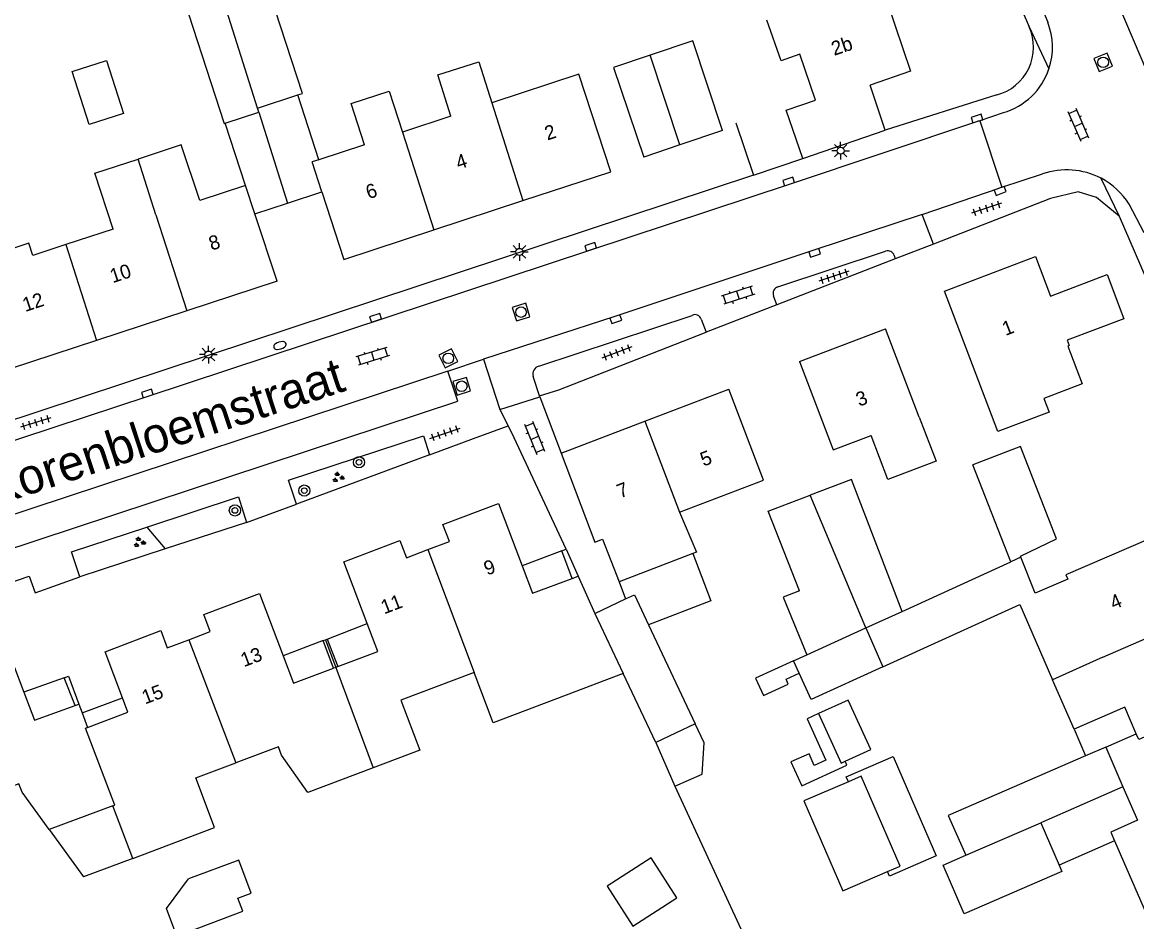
# Model space of a CAD drawing. Extents: x 136000 to 138005, y 398500 to 400500.
# Drawn here: x 137462 to 137540.9, y 398555 to 398618.7 of the extents above; entities that cross this region are included whole.
import ezdxf

# ---------------------------------------------------------------- set-up
doc = ezdxf.new("R2010")
doc.units = 0
for name, color, linetype in [('gg-afsc-muur', 7, 'Continuous'), ('gg-anno-huisnummerreeks BGT', 7, 'Continuous'), ('gg-anno-openbare ruimte label', 7, 'Continuous'), ('gg-bbg-bijgebouw', 7, 'Continuous'), ('gg-bbg-gedigitaliseerde bebouwing', 7, 'Continuous'), ('gg-bbg-gedigitaliseerde bijgebouw', 7, 'Continuous'), ('gg-bbg-hoofdgebouw', 7, 'Continuous'), ('gg-bbg-luifel en loopbrug', 7, 'Continuous'), ('gg-bbg-overig bouwwerk', 7, 'Continuous'), ('gg-bbg-tussenscheiding', 7, 'Continuous'), ('gg-knt-verharding', 7, 'Continuous'), ('gt-grn-groengrens', 7, 'Continuous'), ('gt-grn-vlakafsluiter', 7, 'Continuous'), ('gt-grn-weggrens', 7, 'Continuous'), ('gt-symb-boom', 7, 'Continuous'), ('gt-symb-brandkraan', 7, 'Continuous'), ('gt-symb-groenvak', 7, 'Continuous'), ('gt-symb-klinker verharding', 7, 'Continuous'), ('gt-symb-kolk', 7, 'Continuous'), ('gt-symb-lichtmast', 7, 'Continuous'), ('gt-symb-rioolschacht', 7, 'Continuous'), ('gt-symb-tegel verharding', 7, 'Continuous')]:
    doc.layers.add(name, color=color, linetype=linetype)

# ---------------------------------------------------------------- blocks, each defined once
blk = doc.blocks.new('gt0-RS')
at = {"layer": 'gt-symb-rioolschacht'}
blk.add_lwpolyline([(-0.5, -0.5), (0.5, -0.5), (0.5, 0.5), (-0.5, 0.5)], close=True, dxfattribs=at)
blk.add_circle((0, 0), 0.375, dxfattribs=at)
blk = doc.blocks.new('gt0-KOLK')
at = {"layer": 'gt-symb-kolk'}
blk.add_lwpolyline([(0, 0), (0.375, 0), (0.375, 0.4), (-0.375, 0.4), (-0.375, 0), (0, 0)], dxfattribs=at)
blk = doc.blocks.new('gt0-LMAST')
at = {"layer": 'gt-symb-lichtmast'}
for p, q in [((-0.182, 0.173), (-0.447, 0.438)), ((-0.005, 0.246), (-0.005, 0.621)), ((0.172, 0.173), (0.437, 0.438)), ((-0.255, -0.004), (-0.63, -0.004)), ((-0.182, -0.181), (-0.447, -0.446)), ((-0.005, -0.254), (-0.005, -0.629)), ((0.437, -0.446), (0.172, -0.181)), ((0.245, -0.004), (0.62, -0.004))]:
    blk.add_line(p, q, dxfattribs=at)
blk.add_circle((-0.005, -0.004), 0.25, dxfattribs=at)
blk = doc.blocks.new('gt0-TEG1')
at = {"layer": 'gt-symb-tegel verharding'}
for p, q in [((-1.125, 0), (1.125, 0)), ((-0.9, -0.25), (-0.9, 0.25)), ((-0.45, -0.25), (-0.45, 0.25)), ((0, -0.25), (0, 0.25)), ((0.45, -0.25), (0.45, 0.25)), ((0.9, -0.25), (0.9, 0.25))]:
    blk.add_line(p, q, dxfattribs=at)
blk = doc.blocks.new('gt0-KL1')
at = {"layer": 'gt-symb-klinker verharding'}
for p, q in [((-1.15, 0.3), (1.15, 0.3)), ((-1, -0.3), (-1, 0.3)), ((-0.5, 0.3), (-0.5, 0.45)), ((0, -0.3), (0, 0.3)), ((0.5, 0.3), (0.5, 0.45)), ((1, -0.3), (1, 0.3)), ((-1.15, -0.3), (1.15, -0.3)), ((-0.5, -0.45), (-0.5, -0.3)), ((0.5, -0.45), (0.5, -0.3))]:
    blk.add_line(p, q, dxfattribs=at)
blk = doc.blocks.new('gt0-BR')
at = {"layer": 'gt-symb-brandkraan'}
for centre, radius, start, end in [((-0.244, 0), 0.206, 107.56694, 252.43307), ((0.599, -2.664), 3, 106.89205, 107.56694), ((0, -0.691), 0.938, 73.10799, 106.89205), ((-0.599, -2.664), 3, 72.43309, 73.10799), ((0.244, 0), 0.206, 287.56695, 72.43309), ((0.599, 2.664), 3, 252.43307, 253.10797), ((0, 0.691), 0.938, 253.10797, 286.89206), ((-0.599, 2.664), 3, 286.89206, 287.56695)]:
    blk.add_arc(centre, radius, start, end, dxfattribs=at)
blk = doc.blocks.new('gt0-GRVAK')
at = {"layer": 'gt-symb-groenvak'}
for p, q in [((-0.11, 0.189), (-0.228, 0.24)), ((-0.182, 0.153), (0.088, 0.153)), ((-0.091, 0.211), (-0.156, 0.322)), ((-0.047, 0.214), (-0.047, 0.393)), ((-0.004, 0.211), (0.061, 0.322)), ((0.015, 0.189), (0.133, 0.24)), ((0.262, -0.052), (0.197, 0.059)), ((0.305, -0.049), (0.305, 0.13)), ((0.349, -0.052), (0.414, 0.059)), ((-0.245, -0.228), (-0.363, -0.177)), ((-0.318, -0.264), (-0.047, -0.264)), ((-0.226, -0.206), (-0.291, -0.095)), ((-0.183, -0.203), (-0.183, -0.024)), ((-0.139, -0.206), (-0.074, -0.095)), ((-0.12, -0.228), (-0.002, -0.177)), ((0.243, -0.074), (0.125, -0.023)), ((0.17, -0.11), (0.441, -0.11)), ((0.368, -0.074), (0.486, -0.023))]:
    blk.add_line(p, q, dxfattribs=at)
blk = doc.blocks.new('gt0-BOOM')
at = {"layer": 'gt-symb-boom'}
for radius in [0.4, 0.2]:
    blk.add_circle((0, 0), radius, dxfattribs=at)

msp = doc.modelspace()

# ---------------------------------------------------------------- linework, layer by layer
at = {"layer": 'gg-afsc-muur'}
for p, q in [((137512.539, 398611.634), (137513.796, 398607.926)), ((137513.796, 398607.926), (137517.298, 398609.1)), ((137500.95, 398579.35), (137500.224, 398581.31)), ((137484.037, 398572.996), (137483.302, 398574.952)), ((137483.601, 398575.065), (137484.336, 398573.109)), ((137465.745, 398570.359), (137464.966, 398572.323))]:
    msp.add_line(p, q, dxfattribs=at)
at = {"layer": 'gg-bbg-bijgebouw'}
for p, q in [((137511.592, 398611.085), (137508.582, 398610.069)), ((137508.582, 398610.069), (137506.021, 398609.204)), ((137504.736, 398577.901), (137505.358, 398578.195)), ((137502.557, 398576.871), (137504.736, 398577.901))]:
    msp.add_line(p, q, dxfattribs=at)
msp.add_lwpolyline([(137532.742, 398580.859), (137532.71, 398580.941), (137535.275, 398582.173), (137532.712, 398588.703), (137529.344, 398587.401)], dxfattribs=at)
at = {"layer": 'gg-bbg-gedigitaliseerde bebouwing'}
for p, q in [((137492.359, 398612.087), (137488.923, 398610.958)), ((137486.228, 398610.073), (137483.011, 398609.015)), ((137483.011, 398609.015), (137482.525, 398608.855)), ((137483.221, 398606.741), (137482.525, 398608.855)), ((137477.81, 398607.188), (137474.564, 398606.121)), ((137478.471, 398605.179), (137477.81, 398607.188)), ((137468.418, 398604.101), (137465.084, 398603.005)), ((137525.537, 398590.788), (137523.14, 398597.04)), ((137509.492, 398581.113), (137504.272, 398579.112)), ((137524.325, 398577.025), (137532.038, 398580.538)), ((137504.57, 398572.613), (137500.533, 398571.09)), ((137536.51, 398568.672), (137534.994, 398572.167)), ((137540.103, 398570.231), (137536.51, 398568.672)), ((137540.921, 398568.353), (137540.103, 398570.231)), ((137539.375, 398560.779), (137541.845, 398555.079))]:
    msp.add_line(p, q, dxfattribs=at)
for points in [[(137518.192, 398613.235), (137517.07, 398616.48), (137515.75, 398616.02), (137514.752, 398618.892)], [(137492.359, 398612.087), (137491.427, 398615.034), (137494.342, 398615.956), (137495.263, 398613.041)], [(137503.68, 398608.16), (137501.413, 398615.062), (137495.263, 398613.041)], [(137486.228, 398610.073), (137485.284, 398613.003), (137487.984, 398613.873), (137488.923, 398610.958)], [(137517.298, 398609.1), (137516.123, 398612.534), (137518.192, 398613.235)], [(137474.564, 398606.121), (137473.251, 398610.064), (137470.196, 398609.047)], [(137468.418, 398604.101), (137467.134, 398608.052), (137470.196, 398609.047)], [(137465.084, 398603.005), (137462.735, 398602.232), (137462.452, 398603.094), (137458.62, 398601.834), (137458.922, 398600.917)], [(137517.05, 398594.71), (137519.447, 398588.457), (137522.127, 398589.483)], [(137508.561, 398584.047), (137514.512, 398586.319), (137512.04, 398592.77)], [(137525.537, 398590.788), (137526.731, 398587.674), (137523.322, 398586.367), (137522.127, 398589.483)], [(137508.561, 398584.047), (137509.76, 398581.216), (137509.492, 398581.113)], [(137522.966, 398573.086), (137532.678, 398577.509), (137534.994, 398572.167)], [(137500.533, 398571.09), (137495.352, 398569.135), (137494.009, 398572.695)], [(137546.98, 398570.52), (137541.094, 398567.955), (137540.921, 398568.353)], [(137469.812, 398559.529), (137475.615, 398561.712), (137474.287, 398565.241), (137477.123, 398566.308)], [(137540.995, 398562.245), (137539.116, 398561.377), (137539.375, 398560.779)]]:
    msp.add_lwpolyline(points, dxfattribs=at)
at = {"layer": 'gg-bbg-gedigitaliseerde bijgebouw'}
for p, q in [((137478.659, 398612.674), (137481.503, 398613.598)), ((137476.356, 398611.606), (137478.751, 398612.384)), ((137478.751, 398612.384), (137478.659, 398612.674)), ((137532.038, 398580.538), (137529.344, 398587.401)), ((137505.358, 398578.195), (137506.363, 398576.068)), ((137506.363, 398576.068), (137509.676, 398569.06)), ((137516.636, 398573.524), (137517.586, 398573.956)), ((137517.038, 398572.641), (137516.636, 398573.524)), ((137506.874, 398567.736), (137504.57, 398572.613)), ((137509.676, 398569.06), (137506.874, 398567.736)), ((137538.752, 398567.411), (137537.326, 398566.793)), ((137538.752, 398567.411), (137539.975, 398564.594)), ((137520.518, 398564.963), (137517.371, 398563.597)), ((137539.975, 398564.594), (137534.145, 398562.056)), ((137534.145, 398562.056), (137535.456, 398559.04))]:
    msp.add_line(p, q, dxfattribs=at)
for points in [[(137481.503, 398613.598), (137481.839, 398613.707), (137479.152, 398621.976), (137484.785, 398623.806)], [(137472.811, 398622.268), (137476.283, 398611.582), (137476.356, 398611.606)], [(137511.592, 398611.085), (137509.491, 398617.435), (137506.482, 398616.42)], [(137465.53, 398615.265), (137467.953, 398616.042), (137469.161, 398612.275), (137466.738, 398611.498), (137465.53, 398615.265)], [(137506.482, 398616.42), (137503.882, 398615.542), (137506.021, 398609.204)], [(137524.325, 398577.025), (137520.742, 398586.37), (137517.822, 398585.251)], [(137517.051, 398578.49), (137514.835, 398584.111), (137517.822, 398585.251)], [(137517.051, 398578.49), (137515.911, 398578.021), (137517.586, 398573.956)], [(137522.966, 398573.086), (137517.889, 398570.774), (137517.038, 398572.641)], [(137520.289, 398566.404), (137522.103, 398567.23), (137520.501, 398570.747), (137518.415, 398569.796)], [(137518.415, 398569.796), (137520.017, 398566.28), (137520.289, 398566.404)], [(137537.326, 398566.793), (137527.597, 398562.572), (137528.84, 398559.746)], [(137523.286, 398558.59), (137524.183, 398558.979), (137521.415, 398565.353), (137520.518, 398564.963)], [(137517.371, 398563.597), (137520.139, 398557.223), (137523.286, 398558.59)], [(137505.258, 398554.729), (137508.375, 398556.732), (137506.551, 398559.571), (137503.434, 398557.568), (137505.258, 398554.729)], [(137535.456, 398559.04), (137535.643, 398558.61), (137528.73, 398555.607), (137527.231, 398559.058), (137528.84, 398559.746)]]:
    msp.add_lwpolyline(points, dxfattribs=at)
at = {"layer": 'gg-bbg-hoofdgebouw'}
for p, q in [((137523.138, 398611.099), (137522.068, 398614.294)), ((137517.298, 398609.1), (137523.138, 398611.099)), ((137497.455, 398606.115), (137503.68, 398608.16)), ((137483.221, 398606.741), (137484.78, 398601.95)), ((137491.15, 398604.043), (137497.455, 398606.115)), ((137480.04, 398600.41), (137478.471, 398605.179)), ((137484.78, 398601.95), (137491.15, 398604.043)), ((137480.04, 398600.41), (137473.64, 398598.305)), ((137473.64, 398598.305), (137467.251, 398596.203)), ((137517.05, 398594.71), (137523.14, 398597.04)), ((137467.251, 398596.203), (137461.137, 398594.192)), ((137506.095, 398590.5), (137512.04, 398592.77)), ((137500.16, 398588.234), (137506.095, 398590.5)), ((137500.95, 398579.35), (137501.377, 398579.511)), ((137501.377, 398579.511), (137502.557, 398576.871)), ((137484.196, 398573.056), (137484.037, 398572.996)), ((137484.336, 398573.109), (137484.196, 398573.056)), ((137465.745, 398570.359), (137466.001, 398570.451)), ((137466.001, 398570.451), (137466.232, 398569.832)), ((137466.232, 398569.832), (137466.613, 398568.811)), ((137468.406, 398563.255), (137463.894, 398561.576)), ((137469.812, 398559.529), (137468.406, 398563.255))]:
    msp.add_line(p, q, dxfattribs=at)
for points in [[(137522.75, 398621.73), (137524.91, 398615.281), (137522.068, 398614.294)], [(137536.027, 398596.227), (137536.17, 398595.85), (137536.07, 398595.81), (137537.09, 398593.14), (137534.38, 398592.11), (137534.75, 398591.14), (137531.12, 398589.76), (137527.339, 398599.693), (137533.77, 398602.16), (137534.838, 398599.352)], [(137534.838, 398599.352), (137538.861, 398600.881), (137540.045, 398597.755), (137536.027, 398596.227)], [(137500.16, 398588.234), (137502.567, 398581.928), (137503.09, 398582.127), (137504.272, 398579.112)], [(137490.728, 398581.397), (137492.251, 398581.967), (137491.791, 398583.177), (137495.734, 398584.671), (137497.4, 398580.244)], [(137541.897, 398582.197), (137535.93, 398579.613), (137536.058, 398579.315), (137533.753, 398578.321), (137532.742, 398580.859)], [(137486.426, 398576.16), (137484.779, 398580.54), (137488.739, 398582.042), (137489.202, 398580.825), (137490.728, 398581.397)], [(137497.4, 398580.244), (137498.13, 398578.305), (137500.95, 398579.35)], [(137473.781, 398575.015), (137475.309, 398575.593), (137474.85, 398576.806), (137478.808, 398578.295), (137480.466, 398573.886)], [(137484.336, 398573.109), (137487.172, 398574.175), (137486.426, 398576.16)], [(137455.463, 398572.391), (137456.962, 398572.949), (137456.508, 398574.171), (137460.452, 398575.665), (137462.108, 398571.291)], [(137469.082, 398570.903), (137467.856, 398574.167), (137471.802, 398575.661), (137472.257, 398574.438), (137473.781, 398575.015)], [(137480.466, 398573.886), (137481.201, 398571.93), (137484.037, 398572.996)], [(137494.009, 398572.695), (137488.817, 398570.733), (137490.148, 398567.19), (137486.855, 398565.948)], [(137462.108, 398571.291), (137462.855, 398569.316), (137465.745, 398570.359)], [(137466.613, 398568.811), (137469.465, 398569.886), (137469.082, 398570.903)], [(137486.855, 398565.948), (137482.233, 398564.205), (137480.346, 398566.851), (137480.132, 398567.436), (137477.123, 398566.308)], [(137463.894, 398561.576), (137461.983, 398564.21), (137461.753, 398564.817), (137458.754, 398563.677)]]:
    msp.add_lwpolyline(points, dxfattribs=at)
at = {"layer": 'gg-bbg-luifel en loopbrug'}
for p, q in [((137500.224, 398581.31), (137497.4, 398580.244)), ((137500.224, 398581.31), (137500.524, 398581.421)), ((137500.524, 398581.421), (137501.377, 398579.511)), ((137504.272, 398579.112), (137504.736, 398577.901)), ((137483.601, 398575.065), (137486.426, 398576.16)), ((137483.302, 398574.952), (137480.466, 398573.886)), ((137483.302, 398574.952), (137483.464, 398575.013)), ((137483.464, 398575.013), (137483.601, 398575.065)), ((137483.464, 398575.013), (137484.196, 398573.056)), ((137464.966, 398572.323), (137462.108, 398571.291)), ((137466.232, 398569.832), (137469.082, 398570.903)), ((137536.51, 398568.672), (137537.326, 398566.793)), ((137538.752, 398567.411), (137540.921, 398568.353)), ((137506.874, 398567.736), (137508.214, 398564.651)), ((137539.975, 398564.594), (137540.995, 398562.245)), ((137463.894, 398561.576), (137466.329, 398558.219)), ((137539.375, 398560.779), (137535.456, 398559.04)), ((137469.812, 398559.529), (137466.329, 398558.219))]:
    msp.add_line(p, q, dxfattribs=at)
for points in [[(137509.492, 398581.113), (137510.777, 398577.76), (137506.363, 398576.068)], [(137516.636, 398573.524), (137513.941, 398572.296), (137514.498, 398571.075), (137516.258, 398571.877), (137516.104, 398572.215), (137517.038, 398572.641)], [(137464.966, 398572.323), (137465.262, 398572.432), (137466.001, 398570.451)], [(137518.415, 398569.796), (137517.6, 398569.425), (137518.934, 398566.495), (137518.108, 398566.119), (137517.732, 398566.945), (137516.45, 398566.361), (137517.218, 398564.676), (137520.413, 398566.131), (137520.289, 398566.404)], [(137508.214, 398564.651), (137510.167, 398565.5), (137510.308, 398567.723), (137509.676, 398569.06)], [(137520.518, 398564.963), (137520.373, 398565.297), (137523.696, 398566.741), (137526.609, 398560.033), (137526.75, 398559.708), (137523.427, 398558.265), (137523.286, 398558.59)], [(137472.938, 398554.022), (137477.618, 398555.782), (137477.266, 398556.718), (137478.202, 398557.07), (137477.322, 398559.41), (137473.765, 398558.072)], [(137472.938, 398554.022), (137472.199, 398555.987), (137473.765, 398558.072)]]:
    msp.add_lwpolyline(points, dxfattribs=at)
at = {"layer": 'gg-bbg-overig bouwwerk'}
for p, q in [((137483.011, 398609.015), (137481.503, 398613.598)), ((137478.751, 398612.384), (137480.79, 398605.942)), ((137477.81, 398607.188), (137476.356, 398611.606)), ((137480.79, 398605.942), (137483.221, 398606.741)), ((137478.471, 398605.179), (137480.79, 398605.942))]:
    msp.add_line(p, q, dxfattribs=at)
at = {"layer": 'gg-bbg-tussenscheiding'}
for p, q in [((137478.659, 398612.674), (137475.36, 398623.096)), ((137508.582, 398610.069), (137506.482, 398616.42)), ((137495.263, 398613.041), (137497.455, 398606.115)), ((137488.923, 398610.958), (137491.15, 398604.043)), ((137471.461, 398605.102), (137470.196, 398609.047)), ((137471.461, 398605.102), (137473.64, 398598.305)), ((137465.084, 398603.005), (137467.251, 398596.203)), ((137506.095, 398590.5), (137508.561, 398584.047)), ((137521.748, 398575.852), (137517.822, 398585.251)), ((137490.728, 398581.397), (137494.009, 398572.695)), ((137532.742, 398580.859), (137532.038, 398580.538)), ((137502.557, 398576.871), (137504.57, 398572.613)), ((137521.748, 398575.852), (137524.325, 398577.025)), ((137517.586, 398573.956), (137521.748, 398575.852)), ((137521.748, 398575.852), (137522.966, 398573.086)), ((137538.554, 398573.79), (137544.44, 398576.355)), ((137473.781, 398575.015), (137477.123, 398566.308)), ((137538.554, 398573.79), (137534.994, 398572.167)), ((137484.196, 398573.056), (137486.855, 398565.948)), ((137528.84, 398559.746), (137534.145, 398562.056))]:
    msp.add_line(p, q, dxfattribs=at)
msp.add_lwpolyline([(137468.406, 398563.255), (137468.545, 398563.308), (137466.472, 398568.758), (137466.613, 398568.811)], dxfattribs=at)
at = {"layer": 'gg-knt-verharding'}
for p, q in [((137524.362, 398639.332), (137533.32, 398618.429)), ((137533.447, 398621.628), (137534.644, 398618.746)), ((137531.03, 398613.6), (137523.138, 398611.099)), ((137531.489, 398612.345), (137529.839, 398611.778)), ((137529.839, 398611.778), (137529.699, 398611.734)), ((137529.839, 398611.778), (137531.402, 398607.069)), ((137513.796, 398607.926), (137411.018, 398573.951)), ((137531.402, 398607.069), (137534.277, 398608.005)), ((137525.75, 398605.131), (137531.202, 398606.995)), ((137531.402, 398607.069), (137531.202, 398606.995)), ((137541.479, 398603.839), (137540.419, 398605.86)), ((137526.54, 398603.043), (137525.75, 398605.131)), ((137539.7, 398605.01), (137567.989, 398539.482)), ((137526.54, 398603.043), (137523.84, 398601.993)), ((137523.84, 398601.993), (137515.444, 398598.73)), ((137515.525, 398600.011), (137523.162, 398602.537)), ((137523.774, 398602.231), (137523.84, 398601.993)), ((137515.444, 398598.73), (137510.453, 398596.788)), ((137515.444, 398598.73), (137515.218, 398599.377)), ((137498.585, 398594.388), (137509.457, 398597.991)), ((137510.087, 398597.72), (137510.453, 398596.788)), ((137492.152, 398594.032), (137494.659, 398594.886)), ((137494.659, 398594.886), (137495.833, 398591.314)), ((137492.152, 398594.032), (137440.788, 398577.095)), ((137498.636, 398592.28), (137498.18, 398593.658)), ((137495.833, 398591.314), (137498.653, 398592.23)), ((137498.653, 398592.23), (137498.636, 398592.28)), ((137498.653, 398592.23), (137500.16, 398588.234)), ((137495.833, 398591.314), (137496.418, 398590.165)), ((137493.961, 398589.257), (137496.418, 398590.165)), ((137490.841, 398588.104), (137493.961, 398589.257)), ((137477.881, 398583.314), (137481.427, 398584.609))]:
    msp.add_line(p, q, dxfattribs=at)
for points in [[(137542.746, 398612.73), (137538.612, 398622.458), (137538.07, 398623.634)], [(137415.111, 398573.873), (137470.907, 398592.259), (137516.356, 398607.287), (137529.699, 398611.734)], [(137539.7, 398605.01), (137538.11, 398606.34), (137536.8, 398606.74), (137534.84, 398606.27), (137526.54, 398603.043)], [(137525.75, 398605.131), (137518.067, 398602.616), (137503.981, 398597.906), (137494.659, 398594.886)], [(137498.636, 398592.28), (137500, 398592.725), (137510.453, 398596.788)], [(137441.429, 398574.946), (137492.856, 398591.909), (137492.152, 398594.032)], [(137500.524, 398581.421), (137496.672, 398589.666), (137496.418, 398590.165)], [(137481.427, 398584.609), (137480.858, 398586.309), (137490.409, 398589.464), (137490.841, 398588.104)], [(137470.812, 398583), (137477.307, 398585.133), (137477.881, 398583.314)], [(137466.061, 398579.479), (137465.467, 398581.244), (137470.812, 398583)], [(137425.16, 398566.699), (137462.487, 398579.529), (137462.894, 398578.337), (137466.061, 398579.479)]]:
    msp.add_lwpolyline(points, dxfattribs=at)
for centre, radius, start, end in [((137530.139, 398616.98), 3.496, 284.77285, 24.48483), ((137530.152, 398616.977), 4.828, 341.63642, 21.49752), ((137530.16, 398616.98), 4.821, 286.00518, 341.57931), ((137536.001, 398603.077), 5.221, 62.40788, 109.27934), ((137536.004, 398603.078), 5.219, 32.21677, 62.43112), ((137523.305, 398602.058), 0.5, 20.21999, 106.64991), ((137515.653, 398599.558), 0.471, 105.75236, 202.57259), ((137509.659, 398597.592), 0.447, 16.59008, 116.85916), ((137498.73, 398593.83), 0.576, 104.54295, 197.4145)]:
    msp.add_arc(centre, radius, start, end, dxfattribs=at)
at = {"layer": 'gt-grn-groengrens'}
for p, q in [((137490.841, 398588.104), (137481.427, 398584.609)), ((137470.812, 398583), (137472.115, 398581.443)), ((137477.881, 398583.314), (137472.115, 398581.443)), ((137472.115, 398581.443), (137466.061, 398579.479))]:
    msp.add_line(p, q, dxfattribs=at)
at = {"layer": 'gt-grn-vlakafsluiter'}
msp.add_line((137508.214, 398564.651), (137535.48, 398505.927), dxfattribs=at)
at = {"layer": 'gt-grn-weggrens'}
for p, q in [((137533.32, 398618.429), (137534.734, 398615.456)), ((137538.419, 398607.704), (137539.7, 398605.01))]:
    msp.add_line(p, q, dxfattribs=at)

# ---------------------------------------------------------------- block references
at = {"layer": 'gt-symb-boom'}
for p in [(137485.846, 398587.584), (137481.973, 398585.576), (137477.054, 398584.174)]:
    msp.add_blockref('gt0-BOOM', p, dxfattribs=at)
at = {"layer": 'gt-symb-brandkraan', "rotation": -163.61369434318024}
msp.add_blockref('gt0-BR', (137480.244, 398595.855), dxfattribs=at)
at = {"layer": 'gt-symb-groenvak'}
for p in [(137484.359, 398586.512), (137470.273, 398581.914)]:
    msp.add_blockref('gt0-GRVAK', p, dxfattribs=at)
at = {"layer": 'gt-symb-klinker verharding'}
for p, rotation in [((137536.811, 398611.491), -66.6659587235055), ((137512.695, 398599.422), -161.76430853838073), ((137486.816, 398595.093), -163.0867822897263), ((137498.29, 398589.318), -67.97515406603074)]:
    msp.add_blockref('gt0-KL1', p, dxfattribs=dict(at, rotation=rotation))
at = {"layer": 'gt-symb-kolk'}
for p, rotation in [((137529.699, 398611.734), 17.456558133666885), ((137516.356, 398607.287), 18.308068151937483), ((137531.202, 398606.995), -159.64503881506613), ((137502.328, 398602.652), 18.23569146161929), ((137518.067, 398602.616), -161.87318748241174), ((137487.083, 398597.622), 18.362468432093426), ((137503.981, 398597.906), -161.5106736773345), ((137470.907, 398592.259), 18.23569146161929)]:
    msp.add_blockref('gt0-KOLK', p, dxfattribs=dict(at, rotation=rotation))
at = {"layer": 'gt-symb-lichtmast'}
for p in [(137519.978, 398609.655), (137497.219, 398602.488), (137475.186, 398595.219)]:
    msp.add_blockref('gt0-LMAST', p, dxfattribs=at)
at = {"layer": 'gt-symb-rioolschacht'}
for p, rotation in [((137538.574, 398615.911), -67.87489745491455), ((137497.33, 398598.221), -162.72457972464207), ((137492.171, 398594.948), -63.76806006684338), ((137493.125, 398592.968), -163.14160123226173)]:
    msp.add_blockref('gt0-RS', p, dxfattribs=dict(at, rotation=rotation))
at = {"layer": 'gt-symb-tegel verharding'}
for p, rotation in [((137530.304, 398605.571), -161.69193184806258), ((137519.49, 398600.773), -161.76430853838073), ((137504.114, 398595.363), -159.2628518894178), ((137462.938, 398590.408), -162.72457972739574), ((137491.941, 398589.638), 18.960251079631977)]:
    msp.add_blockref('gt0-TEG1', p, dxfattribs=dict(at, rotation=rotation))

# ---------------------------------------------------------------- texts
at = {"layer": 'gg-anno-huisnummerreeks BGT'}
for s, rotation, p in [('2b', 18.5, (137519.508, 398616.368)), ('2', 18.2, (137499.193, 398610.37)), ('4', 18.2, (137492.897, 398608.301)), ('6', 18.2, (137486.525, 398606.208)), ('8', 18.2, (137475.399, 398602.568)), ('10', 18.2, (137468.389, 398600.262)), ('12', 18.2, (137462.2, 398598.226)), ('1', 21, (137531.649, 398596.527)), ('3', 20.9, (137521.285, 398591.512)), ('5', 20.9, (137510.255, 398587.271)), ('7', 20.9, (137504.348, 398585.016)), ('9', 20.7, (137494.921, 398579.551)), ('11', 20.8, (137487.628, 398576.808)), ('4', 23.5, (137539.322, 398577.117)), ('13', 20.6, (137477.693, 398573.068)), ('15', 20.7, (137470.689, 398570.428))]:
    msp.add_text(s, height=1, rotation=rotation, dxfattribs=at).set_placement(p)
at = {"layer": 'gg-anno-openbare ruimte label'}
msp.add_text('Korenbloemstraat', height=2.5, rotation=18.2, dxfattribs=at).set_placement((137459.946, 398584.442))

doc.saveas('drawing.dxf')
